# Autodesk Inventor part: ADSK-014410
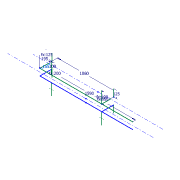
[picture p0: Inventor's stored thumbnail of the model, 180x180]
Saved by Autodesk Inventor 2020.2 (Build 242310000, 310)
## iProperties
Created: 2019-11
Part Number: ADSK-014410
Material: 1.0501 C35
Document SubType Name: Modeling
Designer: lutzd
Density: 7.84 g/cm^3
Appearance: Stahl
VLDS_Profile: Default Part
VLDS_TimeStamp: 2016-07-29
VLDS_FailCnt: 0
VLDS_AcceptCnt: 0
Dimensions: 0x0x0 mm
Mass: 0 kg
DocNumber: ADSK-014410
Folder: 01 - Themengebiete\Simplification\01 - Packaging machine\Parts\
VDS_Category: 3D Komponenten
VDS_NumSchm: Autodesk
VLT_Material: 1.0501 C35
Title: skeleton
Author: lutzd
Revision Number: -
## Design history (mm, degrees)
workplane "Arbeitsebene2"
sketch "Skizze1"
  geometry: L1 (-795, 0)-(795, 0); L2 (795, 0)-(795, 155); L3 (-265, 0)-(-265, 155); 2 further points
  constraints: 6 end point, 2 vertical, 1 coincident, 1 horizontal, 1 midpoint, 1 point on line
  dimensions: "d0" = 1590 distance of L1.start L1.end; "d1" = 155 distance of L1.end L2.end; "d2" = 155 distance of L3.start L3.end (= d1); "d3" = 1060 distance between parallel lines of L2 L3
workplane "Arbeitsebene3"
sketch "Skizze5"
  geometry: L1 (795, 0)-(-795, 0) reference; L2 (265, 0)-(265, 155) reference; L3 (-795, 0)-(-795, 155) reference; 1 further point
sketch "Skizze4"
  geometry: 1 further point
sketch "Skizze2"
  geometry: L1 (-265, 57)-(-265, 257); L2 (600, 57)-(600, 257); L3 (-1152, 0)-(1347, 0) reference; L4 (-265, -57)-(-265, -257); L5 (600, -57)-(600, -257); 10 further points
  constraints: 8 end point, 6 symmetric about line, 4 midpoint, 2 vertical, 1 horizontal alignment
  dimensions: "d4" = 200 distance of L1.start L1.end; "d5" = 200 distance of L2.start L2.end (= d4); "d9" = 100 distance of point (600, 157) L2.end; "d10" = 100 distance of point (-265, 157) L1.end (= d9); "d13" = 195 distance from line of L2 point (795, 57)
workplane "Arbeitsebene1"
sketch "Skizze3"
  geometry: L1 (0, 0)-(0, 125); L2 (1060, 0)-(1060, 125); L3 (-848, -57)-(1378, -57) reference; L4 (1060, -114)-(1060, -239); L5 (0, -114)-(0, -239); 5 further points
  constraints: 8 end point, 4 symmetric about line, 2 vertical
  dimensions: "d7" = 125 distance of L1.start L1.end; "d8" = 125 distance of L2.start L2.end (= d7)
other parameters: "d11" = 57, "d12" = -57 (= -d11)
